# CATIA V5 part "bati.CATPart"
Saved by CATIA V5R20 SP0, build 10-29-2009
Part number: bati
Bounding box of the stored display mesh (mm): x -50 to 30, y -110 to 130, z -70 to 63.987
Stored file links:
  D:\Dropbox\IAO_2012\IAO_2012_991_jambrosino\IAO_2012_991_jambrosino_Catia\Assemblage\bati.CATPart
  D:\Dropbox\IAO_2012\IAO_2012_991_jambrosino\IAO_2012_991_jambrosino_Catia\Assemblage\Ass_IAO_991_skl.CATProduct
  C:\Users\Julien\Desktop\IAO_Mecanisme_991\IAO_Mecanisme_991_CATIA\skl_bati.CATPart
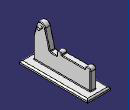
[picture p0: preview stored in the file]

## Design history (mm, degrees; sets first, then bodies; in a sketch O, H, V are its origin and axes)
Set1
  Plane1 "plan_ref_yz": linked copy from another document
  DatumPoint1 to DatumPoint3: linked copy from another document
  Line1: linked copy from another document
Body1 (main body)
  Sketch1 on Plane1, origin (0, 0, 0), H (0, 1, 0), V (0, 0, 1)
    point P1 (-65, 49)
    reference projected point E1 (-65, 49) from vertex of DatumPoint1
    arc A1 centre (-65, 49) radius 15 from (-50.4991, 52.8372) to (-79.5009, 52.8372) ccw
    line L1 (-79.5009, 52.8372) -> (-90, 13.1608)
    line L2 (-50.4991, 52.8372) -> (-33.8712, -10)
    point P6 (0, 0)
    arc A2 centre (0, 0) radius 8 from (8, 0) to (-8, 0) ccw
    point P7 (-8, 0)
    point P8 (8, 0)
    line L3 (-33.8712, -10) -> (-8, -10)
    line L4 (-8, 0) -> (-8, -10)
    point P10 (100, 0)
    point P11 (100, 0)
    reference projected point E2 (100, 0) from vertex of DatumPoint2
    reference projected point E3 (100, 0) from DatumPoint2
    arc A3 centre (100, 0) radius 10 from (110, 0) to (90, 0) ccw
    point P13 (110, 0)
    line L5 (-90, 13.1608) -> (-90, -60)
    line L6 (-90, -60) -> (110, -60)
    line L7 (110, 0) -> (110, -60)
    line L8 (90, 0) -> (8, 0)
    axis line L9 (-65, 110) -> (-65, -90)
    radius A2 = 8
    radius A3 = 10
    radius A1 = 15
    distance L5 L7 = 200
    distance L3 L6 = 50
    length L2 = 65
    coincidence: P1 E1, P6 O, P7 H, P8 H, P11 H, P11 E2, P10 E3, P13 H
    horizontal: L3 H, L6 H, L8 H
    tangency: A3 L3, L1 A1, A1 L2, A3 L7, L4 A2
    vertical: L5 V, L9 V
    symmetry: L1 L2 L9
  Pad1: profile Sketch1, direction (-1, 0, 0), length 20
  Sketch2 on start face of Pad1, origin (0, 0, 0), H (0, 1, 0), V (0, 0, 1)
    circle A1 centre (-65, 49) radius 5
    point P1 (-65, 49)
    reference projected point E1 (-65, 49) from DatumPoint1
    radius A1 = 5
    coincidence: P1 E1
  Pad2: profile Sketch2, direction (1, 0, 0), length 9
  Plane2: type Offset, RefPlane start face of Pad1, Offset 3, reversed
  Sketch3 on face of Pad1 from Sketch1.L6, origin (0, 0, -60), H (1, 0, 0), V (0, -1, 0)
    line L1 (-50, 110) -> (30, 110)
    line L2 (30, 110) -> (30, -130)
    line L3 (30, -130) -> (-50, -130)
    line L4 (-50, -130) -> (-50, 110)
    construction line L5 (-10, 140) -> (-10, -190)
    reference projected line E1 (-20, 90) -> (-20, -110) from edge [end face of Pad1 | face of Pad1 from Sketch1.L6]
    reference projected line E2 (0, 90) -> (0, -110) from edge [face of Pad1 from Sketch1.L6 | start face of Pad1]
    reference projected line E3 (-20, 90) -> (-20, -110) from edge [end face of Pad1 | face of Pad1 from Sketch1.L6]
    axis line L6 (-80, -10) -> (70, -10)
    reference projected line E4 (0, 90) -> (-20, 90) from edge [face of Pad1 from Sketch1.L5 | face of Pad1 from Sketch1.L6]
    reference projected line E5 (0, -110) -> (-20, -110) from edge [face of Pad1 from Sketch1.L6 | face of Pad1 from Sketch1.L7]
    reference projected line E6 (0, 90) -> (-20, 90) from edge [face of Pad1 from Sketch1.L5 | face of Pad1 from Sketch1.L6]
    distance L4 E3 = 30
    distance L1 E6 = 20
    horizontal: L1 H, L3 H, L6 H
    vertical: L2 V, L4 V, L5 V
    symmetry: E1 E2 L5, L4 L2 L5, E4 E5 L6, L3 L1 L6
  Pad3: profile Sketch3, direction (0, 0, -1), length 10
  Fillet1: radius 2, on edge [end face of Pad1 | face of Pad1 from Sketch1.L5]; edge [face of Pad1 from Sketch1.L5 | start face of Pad1]; edge [face of Pad1 from Sketch1.L7 | start face of Pad1]; edge [end face of Pad1 | face of Pad1 from Sketch1.L7]; edge [end face of Pad1 | face of Pad1 from Sketch1.L8]; edge [face of Pad1 from Sketch1.L8 | start face of Pad1]; edge [end face of Pad1 | face of Pad1 from Sketch1.L3]; edge [face of Pad1 from Sketch1.L3 | start face of Pad1]; edge [end face of Pad1 | face of Pad1 from Sketch1.L2]; edge [face of Pad1 from Sketch1.L2 | start face of Pad1]; edge [face of Pad1 from Sketch1.L5 | start face of Pad3]; edge [start face of Pad3 | start face of Pad1]; edge [start face of Pad3 | face of Pad1 from Sketch1.L7]; edge [face of Pad1 from Sketch1.L3 | face of Pad1 from Sketch1.L2]; edge [face of Pad1 from Sketch1.L8 | face of Pad1 from Sketch1.A2]; edge [face of Pad1 from Sketch1.L4 | face of Pad1 from Sketch1.L3]; edge [face of Pad1 from Sketch1.L4 | start face of Pad1]; edge [end face of Pad1 | face of Pad1 from Sketch1.L4]
  Fillet2: radius 5, on edge [start face of Pad3 | face of Pad3 from Sketch3.L2]; edge [start face of Pad3 | face of Pad3 from Sketch3.L1]; edge [start face of Pad3 | face of Pad3 from Sketch3.L4]; edge [start face of Pad3 | face of Pad3 from Sketch3.L3]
